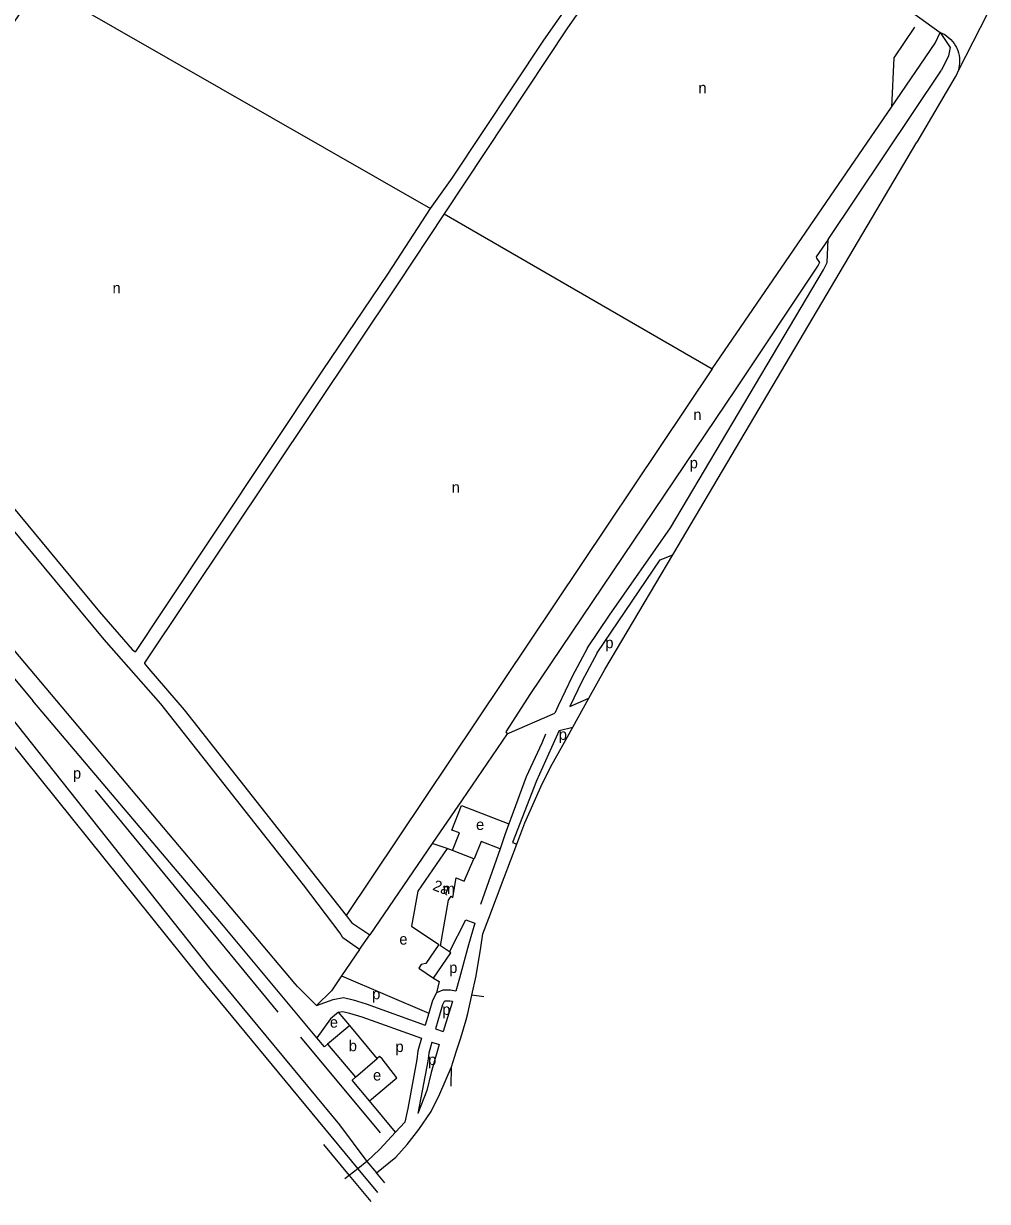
# Model space of a CAD drawing. Extents: x 158142 to 159655, y 385262 to 387204.
# Drawn here: x 159167.3 to 159519.3, y 385261.9 to 385692.2 of the extents above; entities that cross this region are included whole.
import ezdxf

# ---------------------------------------------------------------- set-up
doc = ezdxf.new("R2010")
doc.units = 0
for name, color, linetype in [('BLT_Basislijn', 7, 'Continuous'), ('BLT_Bebouwing', 7, 'Continuous'), ('BLT_Centroide', 7, 'Continuous'), ('BLT_Huisnummer', 7, 'Continuous'), ('BLT_Spoorlijn', 7, 'Continuous'), ('BLT_Vlakafsluiter', 7, 'Continuous')]:
    doc.layers.add(name, color=color, linetype=linetype)

msp = doc.modelspace()

# ---------------------------------------------------------------- linework, layer by layer
at = {"layer": 'BLT_Basislijn'}
for p, q in [((159173.19, 385706.41), (159315.87, 385624.7)), ((159461.07, 385613.29), (159502.46, 385675.17)), ((159507.51, 385672.7), (159493.5, 385648.88)), ((159418.8, 385566.05), (159484.23, 385661.68)), ((159320.87, 385622.75), (159418.8, 385566.05)), ((159418.8, 385566.05), (159285.08, 385366.38)), ((159240.33, 385362.58), (159170.61, 385444.74)), ((159366.81, 385442.73), (159373.66, 385445.73)), ((159343.86, 385432.69), (159361.33, 385440.33)), ((159343.86, 385432.69), (159327.46, 385408.67)), ((159362.9, 385433.98), (159367.81, 385435.16)), ((159193.41, 385412.1), (159260.18, 385331.05)), ((159327.46, 385408.67), (159316.51, 385392.66)), ((159316.51, 385392.66), (159293.69, 385359.25)), ((159321.93, 385390.86), (159316.51, 385392.66)), ((159332.08, 385363.62), (159329.71, 385355.6)), ((159274.38, 385321.74), (159240.33, 385362.58)), ((159289.92, 385353.91), (159293.69, 385359.25)), ((159283.42, 385344.29), (159315.23, 385330.65)), ((159267.33, 385340.44), (159274.24, 385333.51)), ((159286.38, 385326.22), (159282.25, 385331.1)), ((159268.4, 385321.97), (159297.48, 385287.03)), ((159288.44, 385307.27), (159287.29, 385306.25)), ((159293.57, 385298.71), (159287.29, 385306.25)), ((159303.14, 385287.22), (159293.57, 385298.71)), ((159303.14, 385287.22), (159306.48, 385290.85)), ((159297.38, 385280.96), (159303.14, 385287.22)), ((159297.38, 385280.96), (159292.66, 385276.51)), ((159292.66, 385276.51), (159296.19, 385272.32)), ((159299.22, 385268.72), (159296.19, 385272.32))]:
    msp.add_line(p, q, dxfattribs=at)
for points in [[(159415.91, 385766.04), (159411.78, 385759.06), (159372.43, 385700), (159365.86, 385690.69), (159320.87, 385622.75)], [(159357.24, 385686.19), (159367.04, 385700), (159379.74, 385719.15)], [(159471.4, 385712.21), (159476.37, 385708.19), (159481.4, 385704.23), (159486.47, 385700.33), (159491.59, 385696.49), (159496.76, 385692.72), (159501.98, 385689.01)], [(159173.19, 385706.41), (159168.66, 385700), (159100, 385599.65), (159097.11, 385595.62), (159100, 385591.97), (159195.03, 385477.25), (159206.87, 385463.51), (159207.86, 385462.77), (159208.26, 385462.82), (159217.86, 385477.25)], [(158962.37, 385690.61), (158995.04, 385649.67), (159021.29, 385616.98), (159235.31, 385347.11)], [(158964.16, 385693.64), (159070.06, 385565.44), (159170.61, 385444.74)], [(159492.61, 385690.91), (159485.06, 385679.73), (159484.23, 385661.68)], [(159315.87, 385624.7), (159323.79, 385635.7), (159357.24, 385686.19)], [(159484.23, 385661.68), (159500.19, 385685.01), (159501.98, 385689.01)], [(159501.98, 385689.01), (159505.69, 385683.51), (159505.1, 385680.41), (159502.46, 385675.17)], [(159501.98, 385689.01), (159502.85, 385688.63), (159503.68, 385688.17), (159504.47, 385687.64), (159505.22, 385687.05), (159505.91, 385686.4), (159506.54, 385685.69), (159507.12, 385684.94), (159507.62, 385684.13), (159507.99, 385683.43)], [(159507.99, 385683.43), (159508.06, 385683.29), (159508.43, 385682.41), (159508.72, 385681.51), (159508.93, 385680.58), (159509.06, 385679.64), (159509.12, 385678.69), (159509.09, 385677.74), (159508.99, 385676.8), (159508.8, 385675.87), (159508.54, 385674.96)], [(159508.54, 385674.96), (159508.2, 385674.07), (159507.79, 385673.21), (159507.51, 385672.7)], [(159404.32, 385498.11), (159493.5, 385648.88)], [(159320.87, 385622.75), (159303.92, 385597.15), (159211.49, 385458.72), (159211.43, 385458.4), (159212.99, 385456.48), (159225.89, 385441.48), (159285.08, 385366.38)], [(159217.86, 385477.25), (159276.48, 385565.35), (159300.52, 385600.98), (159315.87, 385624.7)], [(159461.07, 385613.29), (159456.77, 385606.96), (159456.82, 385606.48), (159457.97, 385604.87), (159457.45, 385603.96), (159427.38, 385558.82), (159352.37, 385447.42), (159343.43, 385433.45), (159343.86, 385432.69)], [(159373.21, 385464.21), (159381.29, 385476.05), (159403.56, 385508.03), (159459.35, 385602.21), (159460.72, 385604.87), (159461.07, 385613.29)], [(159289.92, 385353.91), (159283.92, 385358.17), (159282.91, 385359.9), (159269.55, 385377.53), (159217.35, 385443.67), (159196.76, 385467.22), (159100, 385583.65), (159095.58, 385588.35), (159093.72, 385590.1), (159077.04, 385564.94)], [(159267.33, 385340.44), (159266.46, 385341.39), (159100, 385538.96), (159085.47, 385554.74), (159077.04, 385564.94)], [(159376.74, 385462.32), (159399.76, 385496.31), (159404.32, 385498.11)], [(159379.57, 385456.27), (159404.32, 385498.11)], [(159373.21, 385464.21), (159367.57, 385453.69), (159362.49, 385442.95), (159361.33, 385440.33)], [(159376.74, 385462.32), (159371.14, 385451.89), (159366.81, 385442.73)], [(159373.66, 385445.73), (159379.57, 385456.27)], [(159367.81, 385435.16), (159373.66, 385445.73)], [(159357.91, 385432.59), (159356.48, 385429.36), (159350.83, 385417.08), (159345.21, 385401.77)], [(159362.9, 385433.98), (159360.12, 385427.72), (159354.53, 385415.55)], [(159356.17, 385413.41), (159359.66, 385420.59), (159365.86, 385431.64), (159367.81, 385435.16)], [(159354.53, 385415.55), (159345.78, 385393.09), (159347.41, 385392.46)], [(159347.41, 385392.46), (159350.35, 385400.22), (159356.17, 385413.41)], [(159323.93, 385390.09), (159326.42, 385396.53), (159323.67, 385397.59), (159327.16, 385406.55), (159344.5, 385399.83)], [(159345.21, 385401.77), (159344.5, 385399.83)], [(159344.5, 385399.83), (159343.04, 385395.84), (159341.27, 385390.76)], [(159341.27, 385390.76), (159334.35, 385393.45), (159331.86, 385387.02), (159331.66, 385387.1)], [(159341.27, 385390.76), (159334.19, 385370.36)], [(159337.18, 385365.37), (159342.79, 385380.24), (159347.41, 385392.46)], [(159285.08, 385366.38), (159287.17, 385363.74), (159293.69, 385359.25)], [(159322.82, 385353.1), (159328.76, 385364.76), (159332.08, 385363.62)], [(159334.22, 385354.66), (159335.03, 385359.66), (159337.18, 385365.37)], [(159329.71, 385355.6), (159326.51, 385343.49), (159325.07, 385338.77)], [(159330.99, 385337.31), (159332.54, 385344.3), (159334.22, 385354.66)], [(159289.92, 385353.91), (159283.42, 385344.29)], [(159235.31, 385347.11), (159282.61, 385289.88), (159292.66, 385276.51)], [(159283.42, 385344.29), (159279.74, 385338.84), (159274.24, 385333.51)], [(159316.98, 385343.53), (159319.02, 385342.27), (159318.08, 385338.07)], [(159318.08, 385338.07), (159316.57, 385335.31), (159315.23, 385330.65)], [(159325.07, 385338.77), (159323.22, 385339.04), (159320.34, 385339.04), (159318.08, 385338.07)], [(159328.85, 385328.28), (159329.5, 385330.54), (159330.99, 385337.31)], [(159274.24, 385333.51), (159280.29, 385335.72), (159284.05, 385336.38), (159287.66, 385335.53), (159292.44, 385334.06), (159313.99, 385326.32)], [(159323.88, 385334.9), (159322.93, 385335.04), (159321.16, 385335.04), (159320.93, 385334.94), (159320.29, 385333.78), (159317.76, 385324.96)], [(159323.88, 385334.9), (159322.59, 385330.67), (159320.52, 385323.97)], [(159282.25, 385331.1), (159279.33, 385328.65), (159274.38, 385321.74)], [(159282.25, 385331.1), (159283.9, 385331.28), (159286.35, 385330.7), (159290.86, 385329.31), (159312.61, 385321.5)], [(159315.23, 385330.65), (159313.99, 385326.32)], [(159317.76, 385324.96), (159320.52, 385323.97)], [(159326.96, 385321.66), (159328.85, 385328.28)], [(159278.32, 385319.4), (159277.15, 385318.41), (159274.38, 385321.74)], [(159312.61, 385321.5), (159311.29, 385316.9), (159310.92, 385313.77), (159307.54, 385295.82), (159306.48, 385290.85)], [(159316.38, 385320.15), (159315.22, 385316.11), (159314.87, 385313.17), (159311.27, 385294.02)], [(159316.38, 385320.15), (159319, 385319.2)], [(159325.4, 385316.9), (159326.96, 385321.66)], [(159319, 385319.2), (159316.14, 385308.97), (159314.56, 385302.46), (159311.27, 385294.02)], [(159323.52, 385311.14), (159325.4, 385316.9)], [(159293.57, 385298.71), (159303.58, 385307.06), (159298.24, 385313.95), (159297.31, 385314.92), (159296.42, 385314.15)], [(159296.19, 385272.32), (159303.26, 385278.03), (159307.36, 385282.68), (159311.65, 385288.21), (159316.11, 385294.82), (159319.32, 385301.25), (159323.52, 385311.14)], [(159296.88, 385271.5), (159296.47, 385271.99)]]:
    msp.add_lwpolyline(points, dxfattribs=at)
at = {"layer": 'BLT_Bebouwing'}
for p, q in [((159296.42, 385314.15), (159286.38, 385326.22)), ((159278.32, 385319.4), (159288.44, 385307.27)), ((159288.44, 385307.27), (159296.42, 385314.15))]:
    msp.add_line(p, q, dxfattribs=at)
for points in [[(159321.93, 385390.86), (159311.29, 385375.2), (159308.98, 385362.5)], [(159323.93, 385390.09), (159321.93, 385390.86)], [(159331.66, 385387.1), (159323.93, 385390.09)], [(159322.82, 385353.1), (159319.54, 385355.33), (159322.4, 385371.96), (159323.42, 385373.42), (159324.06, 385372.97), (159325.31, 385380.08), (159328.23, 385378.95), (159331.66, 385387.1)], [(159308.98, 385362.5), (159318.91, 385355.72), (159314.23, 385348.8), (159312.45, 385348.45), (159311.61, 385347.18), (159316.98, 385343.53)], [(159316.98, 385343.53), (159323.25, 385352.79), (159322.82, 385353.1)], [(159286.38, 385326.22), (159278.32, 385319.4)]]:
    msp.add_lwpolyline(points, dxfattribs=at)
at = {"layer": 'BLT_Spoorlijn'}
for p, q in [((159231.45, 385343.93), (159289.35, 385273.88)), ((159276.86, 385282.68), (159286.23, 385271.4)), ((159289.35, 385273.88), (159296.56, 385265.16)), ((159286.23, 385271.4), (159294.12, 385261.91))]:
    msp.add_line(p, q, dxfattribs=at)
msp.add_lwpolyline([(159161.73, 385430.64), (159231.45, 385343.93)], dxfattribs=at)
at = {"layer": 'BLT_Vlakafsluiter'}
for p, q in [((159519.27, 385695.95), (159508.54, 385674.96)), ((159335.31, 385336.7), (159330.99, 385337.31)), ((159323.4, 385304.02), (159323.52, 385311.14)), ((159289.35, 385273.88), (159286.23, 385271.4)), ((159292.66, 385276.51), (159289.35, 385273.88)), ((159286.23, 385271.4), (159284.63, 385270.12))]:
    msp.add_line(p, q, dxfattribs=at)

# ---------------------------------------------------------------- texts
at = {"layer": 'BLT_Centroide'}
for s, p in [('n', (159413.74, 385666.75)), ('n', (159199.75, 385593.62)), ('n', (159411.86, 385547.38)), ('p', (159410.55, 385529.74)), ('n', (159323.63, 385520.82)), ('p', (159379.74, 385464.03)), ('p', (159362.73, 385430.54)), ('p', (159185.32, 385416.37)), ('e', (159332.52, 385397.61)), ('m', (159320.31, 385374.17)), ('e', (159304.5, 385355.75)), ('p', (159322.72, 385345.37)), ('p', (159294.57, 385335.76)), ('p', (159320.18, 385330.06)), ('e', (159279.13, 385325.41)), ('b', (159286.04, 385316.8)), ('p', (159303.1, 385316.49)), ('p', (159315.02, 385311.74)), ('e', (159294.9, 385306.08))]:
    msp.add_text(s, height=4, dxfattribs=at).set_placement(p)
at = {"layer": 'BLT_Huisnummer'}
msp.add_text('2a', height=4, rotation=338.822, dxfattribs=at).set_placement((159316.38, 385375.81))

doc.saveas('drawing.dxf')
